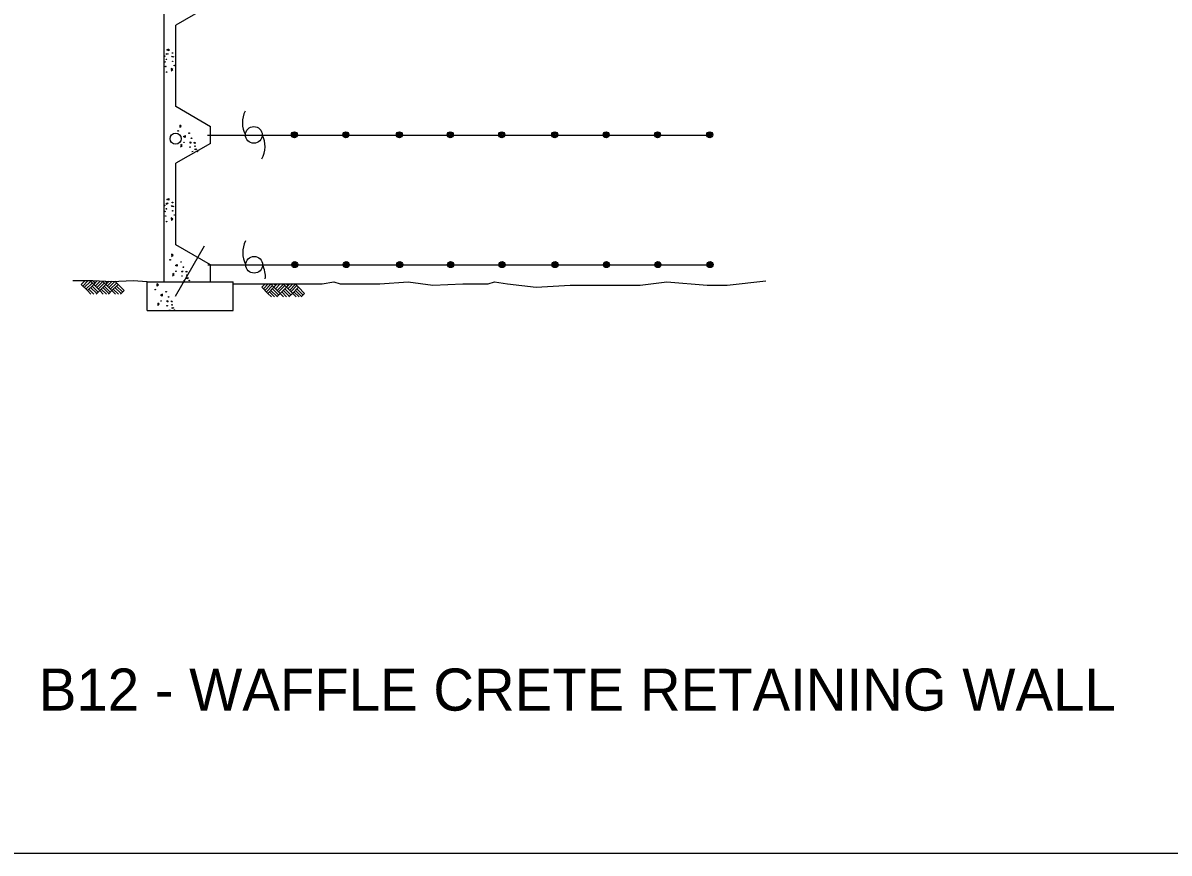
# Model space of a CAD drawing. Extents: x -0.04 to 2.79, y -0.02 to 1.81.
# Drawn here: x 0.1828 to 0.4662, y 0.4885 to 0.6938 of the extents above; entities that cross this region are included whole.
import ezdxf

# ---------------------------------------------------------------- set-up
doc = ezdxf.new("R2010")
doc.units = 0
doc.layers.add('Level 1', color=7, linetype='Continuous')
doc.layers.add('Level 2', color=7, linetype='Continuous')

msp = doc.modelspace()

# ---------------------------------------------------------------- linework, layer by layer
msp.add_line((0.11656352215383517, 0.48847341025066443), (2.517841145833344, 0.48847341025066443))
at = {"layer": 'Level 1'}
for p, q in [((0.21775933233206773, 0.6298094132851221), (0.21775933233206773, 0.8241991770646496)), ((0.22917392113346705, 0.6982285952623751), (0.2206300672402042, 0.6933073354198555)), ((0.2206300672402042, 0.6731438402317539), (0.2206300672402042, 0.6933073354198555)), ((0.22917392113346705, 0.668154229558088), (0.2206300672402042, 0.6731438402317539)), ((0.228490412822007, 0.6661037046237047), (0.3526155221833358, 0.6661037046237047)), ((0.22917392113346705, 0.6639848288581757), (0.22917392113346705, 0.6682909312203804)), ((0.22917392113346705, 0.6640531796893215), (0.2206300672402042, 0.6591319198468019)), ((0.2206300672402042, 0.6389684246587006), (0.2206300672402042, 0.6591319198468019)), ((0.2276702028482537, 0.6386266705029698), (0.2204933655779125, 0.6261868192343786)), ((0.22917392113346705, 0.6339788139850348), (0.2206300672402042, 0.6389684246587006)), ((0.22855876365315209, 0.6339788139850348), (0.35268387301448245, 0.6339788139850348)), ((0.22917392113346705, 0.6298094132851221), (0.22917392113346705, 0.6341155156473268)), ((0.1972540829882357, 0.6291259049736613), (0.19807429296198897, 0.6299461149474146)), ((0.19882615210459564, 0.6276221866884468), (0.1972540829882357, 0.6291259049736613)), ((0.19766418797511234, 0.6287157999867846), (0.19882615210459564, 0.6299461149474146)), ((0.19800594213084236, 0.6283740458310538), (0.19957801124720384, 0.6298777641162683)), ((0.198416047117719, 0.6279639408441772), (0.19991976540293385, 0.6294676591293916)), ((0.19882615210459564, 0.6276221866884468), (0.2003298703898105, 0.6291259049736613)), ((0.2003298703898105, 0.6291259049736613), (0.19950966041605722, 0.6299461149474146)), ((0.20067162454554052, 0.6294676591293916), (0.2002615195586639, 0.6299461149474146)), ((0.2003298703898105, 0.6291259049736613), (0.20108172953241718, 0.6299461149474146)), ((0.2003298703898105, 0.6291259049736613), (0.20108172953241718, 0.6299461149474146)), ((0.20183358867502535, 0.6276221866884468), (0.2003298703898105, 0.6291259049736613)), ((0.20067162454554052, 0.6287157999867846), (0.20190193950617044, 0.6299461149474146)), ((0.20108172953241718, 0.6298777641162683), (0.2010133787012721, 0.6299461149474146)), ((0.20108172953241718, 0.6283740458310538), (0.20258544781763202, 0.6298777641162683)), ((0.20142348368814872, 0.6279639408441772), (0.20292720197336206, 0.6294676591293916)), ((0.20183358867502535, 0.6276221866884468), (0.2033373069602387, 0.6291259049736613)), ((0.2033373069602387, 0.6291259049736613), (0.2025170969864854, 0.6299461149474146)), ((0.20367906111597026, 0.6294676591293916), (0.2032689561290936, 0.6299461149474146)), ((0.2033373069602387, 0.6291259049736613), (0.20415751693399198, 0.6299461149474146)), ((0.2033373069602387, 0.6291259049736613), (0.20415751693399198, 0.6299461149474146)), ((0.20572958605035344, 0.6267336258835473), (0.2033373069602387, 0.6291259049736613)), ((0.20367906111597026, 0.6287157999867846), (0.20490937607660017, 0.6299461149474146)), ((0.2040891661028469, 0.6298777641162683), (0.20402081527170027, 0.6299461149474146)), ((0.2040891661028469, 0.6283740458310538), (0.20559288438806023, 0.6298777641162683)), ((0.2044309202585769, 0.6279639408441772), (0.20593463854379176, 0.6294676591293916)), ((0.20484102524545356, 0.6276221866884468), (0.2063447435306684, 0.6291259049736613)), ((0.2063447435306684, 0.6291259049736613), (0.20552453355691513, 0.6299461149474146)), ((0.20784846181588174, 0.6276221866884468), (0.2063447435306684, 0.6291259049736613)), ((0.2135215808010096, 0.6298094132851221), (0.23484704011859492, 0.6298094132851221)), ((0.2135215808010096, 0.6227009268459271), (0.2135215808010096, 0.6298094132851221)), ((0.23484704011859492, 0.6227009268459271), (0.23484704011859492, 0.6298094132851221)), ((0.2418871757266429, 0.6284423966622), (0.24270738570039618, 0.6292626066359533)), ((0.24229728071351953, 0.6281006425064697), (0.24345924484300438, 0.6292626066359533)), ((0.2426390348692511, 0.627690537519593), (0.2441427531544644, 0.6291942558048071)), ((0.2448946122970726, 0.6284423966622), (0.2441427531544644, 0.6292626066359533)), ((0.2448946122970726, 0.6284423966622), (0.2457148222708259, 0.6292626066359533)), ((0.24530471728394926, 0.6288525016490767), (0.2448946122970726, 0.6292626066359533)), ((0.2448946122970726, 0.6284423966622), (0.2457148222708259, 0.6292626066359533)), ((0.24530471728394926, 0.6281006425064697), (0.24646668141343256, 0.6292626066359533)), ((0.2457148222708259, 0.6291942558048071), (0.24564647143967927, 0.6292626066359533)), ((0.2457148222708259, 0.627690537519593), (0.24721854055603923, 0.6291942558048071)), ((0.2479703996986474, 0.6284423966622), (0.24715018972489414, 0.6292626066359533)), ((0.24831215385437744, 0.6288525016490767), (0.2479020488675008, 0.6292626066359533)), ((0.2479703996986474, 0.6284423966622), (0.2487906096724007, 0.6292626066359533)), ((0.2479703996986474, 0.6284423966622), (0.2487906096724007, 0.6292626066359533)), ((0.24831215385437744, 0.6281006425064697), (0.24954246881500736, 0.6292626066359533)), ((0.24872225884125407, 0.6291942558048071), (0.24865390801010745, 0.6292626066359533)), ((0.24872225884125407, 0.627690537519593), (0.25022597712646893, 0.6291942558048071)), ((0.2509778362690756, 0.6284423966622), (0.25015762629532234, 0.6292626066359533)), ((0.19964636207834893, 0.6267336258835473), (0.19882615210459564, 0.6276221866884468)), ((0.20039822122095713, 0.6267336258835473), (0.1991679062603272, 0.6279639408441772)), ((0.20108172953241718, 0.6268703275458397), (0.19957801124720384, 0.6283740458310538)), ((0.20142348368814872, 0.6272120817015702), (0.19991976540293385, 0.6287157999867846)), ((0.20094502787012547, 0.6267336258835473), (0.20183358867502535, 0.6276221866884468)), ((0.20265379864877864, 0.6267336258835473), (0.20183358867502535, 0.6276221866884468)), ((0.20347400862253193, 0.6267336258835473), (0.2021753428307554, 0.6279639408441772)), ((0.2040891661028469, 0.6268703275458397), (0.20258544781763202, 0.6283740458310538)), ((0.2044309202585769, 0.6272120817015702), (0.20292720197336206, 0.6287157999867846)), ((0.20395246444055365, 0.6267336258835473), (0.20484102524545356, 0.6276221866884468)), ((0.2064814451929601, 0.6267336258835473), (0.20518277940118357, 0.6279639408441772)), ((0.20709660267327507, 0.6268703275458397), (0.20559288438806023, 0.6283740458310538)), ((0.20750670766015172, 0.6272120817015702), (0.20593463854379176, 0.6287157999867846)), ((0.20695990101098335, 0.6267336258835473), (0.20784846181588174, 0.6276221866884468)), ((0.24339089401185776, 0.6269386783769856), (0.2418871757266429, 0.6284423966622)), ((0.24304913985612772, 0.6273487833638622), (0.24455285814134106, 0.6288525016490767)), ((0.24339089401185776, 0.6269386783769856), (0.2448946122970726, 0.6284423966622)), ((0.24427945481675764, 0.6260501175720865), (0.24339089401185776, 0.6269386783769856)), ((0.2450313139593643, 0.6260501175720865), (0.2438009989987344, 0.6273487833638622)), ((0.2457148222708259, 0.6261868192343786), (0.2441427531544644, 0.627690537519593)), ((0.2460565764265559, 0.6265969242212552), (0.24455285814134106, 0.6281006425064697)), ((0.24646668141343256, 0.6269386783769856), (0.2448946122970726, 0.6284423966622)), ((0.24557812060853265, 0.6260501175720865), (0.24646668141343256, 0.6269386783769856)), ((0.2460565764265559, 0.6273487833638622), (0.24756029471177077, 0.6288525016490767)), ((0.24646668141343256, 0.6269386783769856), (0.2479703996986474, 0.6284423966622)), ((0.24728689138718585, 0.6260501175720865), (0.24646668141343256, 0.6269386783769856)), ((0.2480387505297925, 0.6260501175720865), (0.24680843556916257, 0.6273487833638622)), ((0.24872225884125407, 0.6261868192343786), (0.24721854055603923, 0.627690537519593)), ((0.2490640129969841, 0.6265969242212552), (0.24756029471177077, 0.6281006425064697)), ((0.2503626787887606, 0.6260501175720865), (0.2479703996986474, 0.6284423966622)), ((0.24858555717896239, 0.6260501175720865), (0.24947411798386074, 0.6269386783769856)), ((0.2490640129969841, 0.6273487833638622), (0.25056773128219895, 0.6288525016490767)), ((0.24947411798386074, 0.6269386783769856), (0.2509778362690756, 0.6284423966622)), ((0.2511145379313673, 0.6260501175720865), (0.2498158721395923, 0.6273487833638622)), ((0.2517296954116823, 0.6261868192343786), (0.25022597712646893, 0.627690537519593)), ((0.25207144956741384, 0.6265969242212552), (0.25056773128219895, 0.6281006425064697)), ((0.25248155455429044, 0.6269386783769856), (0.2509778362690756, 0.6284423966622)), ((0.25159299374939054, 0.6260501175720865), (0.25248155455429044, 0.6269386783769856)), ((0.2135215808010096, 0.6227009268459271), (0.23484704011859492, 0.6227009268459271))]:
    msp.add_line(p, q, dxfattribs=at)
for points in [[(0.2135215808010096, 0.6298094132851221), (0.21010403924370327, 0.6300828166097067), (0.20484102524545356, 0.6298094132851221), (0.20012481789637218, 0.6300828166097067), (0.1951352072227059, 0.6300828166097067)], [(0.23484704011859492, 0.6292626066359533), (0.2376494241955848, 0.6292626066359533), (0.24243398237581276, 0.6292626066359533), (0.24632997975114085, 0.6292626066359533), (0.2528916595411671, 0.6292626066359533), (0.2568560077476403, 0.6292626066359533), (0.2597267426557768, 0.6298094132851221), (0.2612988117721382, 0.6292626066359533), (0.26792884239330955, 0.6292626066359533), (0.27107298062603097, 0.6292626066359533), (0.27811311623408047, 0.6298094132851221), (0.2841963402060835, 0.6289892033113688), (0.291578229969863, 0.6292626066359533), (0.2978665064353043, 0.6292626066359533), (0.2994385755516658, 0.6298094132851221), (0.3026510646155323, 0.6292626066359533), (0.3096912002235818, 0.6285107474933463), (0.3180983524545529, 0.6289892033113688), (0.32677890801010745, 0.6289892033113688), (0.33545946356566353, 0.6289892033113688), (0.3420211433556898, 0.6298094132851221), (0.3520003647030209, 0.6289892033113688), (0.35698997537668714, 0.6289892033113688), (0.3664907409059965, 0.6300828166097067)]]:
    msp.add_lwpolyline(points, dxfattribs=at)
for centre, radius in [((0.2205845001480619, 0.665208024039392), 0.0013812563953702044), ((0.23991746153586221, 0.6661378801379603), 0.002070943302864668), ((0.2499598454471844, 0.6661744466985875), 0.0007409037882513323), ((0.2499598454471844, 0.6661744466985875), 0.0005745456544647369), ((0.2499598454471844, 0.6661744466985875), 0.0004212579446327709), ((0.2499598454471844, 0.6661744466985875), 0.0002128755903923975), ((0.26267167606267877, 0.6661744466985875), 0.0007409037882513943), ((0.26267167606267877, 0.6661744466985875), 0.0005745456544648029), ((0.26267167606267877, 0.6661744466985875), 0.0004212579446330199), ((0.26267167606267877, 0.6661744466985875), 0.0002128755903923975), ((0.2759146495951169, 0.6661744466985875), 0.0007409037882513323), ((0.2759146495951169, 0.6661744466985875), 0.0005745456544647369), ((0.2759146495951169, 0.6661744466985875), 0.0004212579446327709), ((0.2759146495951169, 0.6661744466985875), 0.0002128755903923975), ((0.2884940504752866, 0.6661744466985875), 0.0007409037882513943), ((0.2884940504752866, 0.6661744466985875), 0.0005745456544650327), ((0.2884940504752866, 0.6661744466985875), 0.00042125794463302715), ((0.2884940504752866, 0.6661744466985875), 0.0002128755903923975), ((0.30120730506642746, 0.6661744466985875), 0.0007409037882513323), ((0.30120730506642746, 0.6661744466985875), 0.0005745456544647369), ((0.30120730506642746, 0.6661744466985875), 0.0004212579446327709), ((0.30120730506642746, 0.6661744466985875), 0.0002128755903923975), ((0.31431784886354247, 0.6661744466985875), 0.0007409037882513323), ((0.31431784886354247, 0.6661744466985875), 0.0005745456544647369), ((0.31431784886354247, 0.6661744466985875), 0.0004212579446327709), ((0.31431784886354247, 0.6661744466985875), 0.00021287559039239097), ((0.32702967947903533, 0.6661744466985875), 0.0007409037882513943), ((0.32702967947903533, 0.6661744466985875), 0.0005745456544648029), ((0.32702967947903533, 0.6661744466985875), 0.0004212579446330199), ((0.32702967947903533, 0.6661744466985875), 0.00021287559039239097), ((0.3397429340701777, 0.6661744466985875), 0.0007409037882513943), ((0.3397429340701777, 0.6661744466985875), 0.0005745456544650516), ((0.3397429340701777, 0.6661744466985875), 0.00042125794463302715), ((0.3397429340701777, 0.6661744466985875), 0.00021287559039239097), ((0.3526455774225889, 0.6661744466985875), 0.0007409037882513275), ((0.3526455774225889, 0.6661744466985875), 0.0005745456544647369), ((0.3526455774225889, 0.6661744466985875), 0.00042125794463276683), ((0.3526455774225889, 0.6661744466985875), 0.0002128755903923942), ((0.24000930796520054, 0.6340201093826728), 0.0020709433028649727), ((0.25004386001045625, 0.6340566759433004), 0.0007409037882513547), ((0.26275569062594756, 0.6340566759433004), 0.0007409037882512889), ((0.27599866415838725, 0.6340566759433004), 0.0007409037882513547), ((0.28857806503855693, 0.6340566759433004), 0.0007409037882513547), ((0.3012913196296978, 0.6340566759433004), 0.0007409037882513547), ((0.3144018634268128, 0.6340566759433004), 0.0007409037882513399), ((0.32711369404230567, 0.6340566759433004), 0.0007409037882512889), ((0.33982694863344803, 0.6340566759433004), 0.0007409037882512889), ((0.35272959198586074, 0.6340566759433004), 0.000740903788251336), ((0.25004386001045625, 0.6340566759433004), 0.0005745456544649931), ((0.25004386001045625, 0.6340566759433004), 0.00042125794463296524), ((0.25004386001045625, 0.6340566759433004), 0.0002128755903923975), ((0.26275569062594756, 0.6340566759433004), 0.0005745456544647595), ((0.26275569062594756, 0.6340566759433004), 0.00042125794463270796), ((0.26275569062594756, 0.6340566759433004), 0.0002128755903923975), ((0.27599866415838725, 0.6340566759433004), 0.0005745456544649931), ((0.27599866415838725, 0.6340566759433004), 0.00042125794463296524), ((0.27599866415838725, 0.6340566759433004), 0.0002128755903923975), ((0.28857806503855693, 0.6340566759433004), 0.0005745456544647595), ((0.28857806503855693, 0.6340566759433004), 0.00042125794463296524), ((0.28857806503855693, 0.6340566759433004), 0.0002128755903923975), ((0.3012913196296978, 0.6340566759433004), 0.0005745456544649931), ((0.3012913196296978, 0.6340566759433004), 0.00042125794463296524), ((0.3012913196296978, 0.6340566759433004), 0.0002128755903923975), ((0.3144018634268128, 0.6340566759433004), 0.0005745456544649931), ((0.3144018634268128, 0.6340566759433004), 0.00042125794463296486), ((0.3144018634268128, 0.6340566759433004), 0.00021287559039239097), ((0.32711369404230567, 0.6340566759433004), 0.0005745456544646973), ((0.32711369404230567, 0.6340566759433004), 0.0004212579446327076), ((0.32711369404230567, 0.6340566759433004), 0.00021287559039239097), ((0.33982694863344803, 0.6340566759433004), 0.0005745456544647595), ((0.33982694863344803, 0.6340566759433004), 0.0004212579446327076), ((0.33982694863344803, 0.6340566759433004), 0.00021287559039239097), ((0.35272959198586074, 0.6340566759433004), 0.0005745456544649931), ((0.35272959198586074, 0.6340566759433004), 0.0004212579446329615), ((0.35272959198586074, 0.6340566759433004), 0.0002128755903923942)]:
    msp.add_circle(centre, radius, dxfattribs=at)
for centre, radius, start, end in [((0.24346539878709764, 0.6691370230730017), 0.006373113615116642, 152.8748638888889, 208.15988888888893), ((0.23631612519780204, 0.663223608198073), 0.006373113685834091, 331.8401111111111, 27.125136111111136), ((0.24355724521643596, 0.6370192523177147), 0.006373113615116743, 152.8748638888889, 208.15988888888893), ((0.23640797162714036, 0.6311058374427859), 0.006373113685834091, 354.5283111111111, 27.125136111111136)]:
    msp.add_arc(centre, radius, start, end, dxfattribs=at)
at = {"layer": 'Level 2'}
for points in [[(0.2187162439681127, 0.6861988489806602), (0.21830613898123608, 0.6859937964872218), (0.21830613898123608, 0.6862671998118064), (0.2187162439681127, 0.6861988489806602)], [(0.21892129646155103, 0.6873608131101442), (0.21892129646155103, 0.6869507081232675), (0.2184428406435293, 0.6872241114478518), (0.21892129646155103, 0.6874291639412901)], [(0.22001490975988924, 0.6854469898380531), (0.2197415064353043, 0.6854469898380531), (0.2196048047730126, 0.6856520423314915), (0.22015161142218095, 0.6854469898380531)], [(0.2194681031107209, 0.6820294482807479), (0.21987820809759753, 0.6823028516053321), (0.2194681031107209, 0.6825762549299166), (0.219536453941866, 0.6819610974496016)], [(0.2215869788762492, 0.6680175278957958), (0.22199708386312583, 0.6682909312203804), (0.2215869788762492, 0.6685643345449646), (0.22165532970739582, 0.6679491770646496)], [(0.22295399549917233, 0.6659670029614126), (0.22295399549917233, 0.6654885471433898), (0.2225438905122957, 0.6657619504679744), (0.22302234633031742, 0.666035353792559)], [(0.2217920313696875, 0.6632329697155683), (0.22220213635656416, 0.6635063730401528), (0.22186038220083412, 0.6637797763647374), (0.22192873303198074, 0.6631646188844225)], [(0.22438936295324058, 0.6641215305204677), (0.22418431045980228, 0.6641215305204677), (0.22418431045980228, 0.6643949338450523), (0.22438936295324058, 0.6641215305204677)], [(0.2254829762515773, 0.6641215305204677), (0.22527792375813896, 0.6640531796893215), (0.22520957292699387, 0.6643265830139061), (0.2254829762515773, 0.664189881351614)], [(0.22493616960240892, 0.6620026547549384), (0.2245944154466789, 0.6619343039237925)], [(0.22582473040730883, 0.6626178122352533), (0.2254146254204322, 0.662412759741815), (0.2254146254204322, 0.6626861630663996), (0.22582473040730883, 0.6626178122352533)], [(0.2187162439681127, 0.6492210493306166), (0.21830613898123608, 0.648947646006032), (0.21830613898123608, 0.6492894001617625), (0.2187162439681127, 0.6492210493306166)], [(0.21892129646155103, 0.6503830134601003), (0.21892129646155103, 0.6499729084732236), (0.2184428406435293, 0.650177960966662), (0.21892129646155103, 0.6504513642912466)], [(0.22001490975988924, 0.6484691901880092), (0.2197415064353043, 0.6484691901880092), (0.2196048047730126, 0.6486742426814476), (0.22015161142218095, 0.6484691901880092)], [(0.2194681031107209, 0.645051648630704), (0.21987820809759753, 0.6453250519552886), (0.2194681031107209, 0.6455984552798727), (0.219536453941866, 0.6449832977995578)], [(0.219536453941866, 0.6360976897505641), (0.22001490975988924, 0.6363710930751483), (0.2196048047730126, 0.6366444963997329), (0.21967315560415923, 0.6360293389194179)], [(0.22097182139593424, 0.634047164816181), (0.22097182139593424, 0.6336370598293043), (0.22056171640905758, 0.6338421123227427), (0.22097182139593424, 0.6341155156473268)], [(0.22240718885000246, 0.632201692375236), (0.22213378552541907, 0.6322700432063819), (0.22220213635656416, 0.6325434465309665), (0.22240718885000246, 0.6322700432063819)], [(0.2235008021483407, 0.6322700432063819), (0.22322739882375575, 0.632201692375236), (0.22315904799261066, 0.6324067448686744), (0.2235008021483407, 0.6323383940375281)], [(0.21591385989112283, 0.6287841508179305), (0.2163239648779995, 0.6290575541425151), (0.21591385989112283, 0.6293309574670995), (0.21598221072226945, 0.6287157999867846)], [(0.21980985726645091, 0.6313131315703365), (0.22021996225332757, 0.6315865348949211), (0.21987820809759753, 0.6318599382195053), (0.21987820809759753, 0.6312447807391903)], [(0.22288564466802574, 0.6300828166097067), (0.2225438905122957, 0.6300144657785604)], [(0.22377420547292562, 0.6307663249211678), (0.22343245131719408, 0.6305612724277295), (0.22343245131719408, 0.6308346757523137), (0.22377420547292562, 0.6307663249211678)], [(0.21728087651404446, 0.6267336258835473), (0.21728087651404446, 0.6262551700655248), (0.21687077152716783, 0.6265285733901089), (0.21734922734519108, 0.6268019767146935)], [(0.21611891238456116, 0.6239995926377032), (0.21652901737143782, 0.6242729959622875), (0.21618726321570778, 0.624546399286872), (0.21625561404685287, 0.623931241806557)], [(0.2187162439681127, 0.6248881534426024), (0.21851119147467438, 0.6248881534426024), (0.21851119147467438, 0.625161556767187), (0.2187162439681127, 0.6248881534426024)], [(0.21980985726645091, 0.6248881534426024), (0.2196048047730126, 0.6248198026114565), (0.219536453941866, 0.6250932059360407), (0.21980985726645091, 0.6249565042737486)], [(0.22015161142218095, 0.6233844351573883), (0.2197415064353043, 0.62317938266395), (0.2197415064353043, 0.6234527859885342), (0.22015161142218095, 0.6233844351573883)], [(0.21926305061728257, 0.6227692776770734), (0.21892129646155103, 0.6227009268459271)]]:
    msp.add_lwpolyline(points, dxfattribs=at)
for centre, radius in [((0.21980549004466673, 0.6864112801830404), 7.404673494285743e-05), ((0.21785490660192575, 0.6856301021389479), 7.404673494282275e-05), ((0.21795312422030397, 0.6842053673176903), 7.404673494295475e-05), ((0.2181402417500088, 0.6830713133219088), 7.404673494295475e-05), ((0.21831766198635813, 0.684836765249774), 7.404673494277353e-05), ((0.21984999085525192, 0.6843466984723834), 7.404673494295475e-05), ((0.22026219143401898, 0.6833063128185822), 7.404673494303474e-05), ((0.21834738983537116, 0.681675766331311), 7.404673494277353e-05), ((0.2212211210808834, 0.6671185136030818), 7.404673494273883e-05), ((0.2239246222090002, 0.666583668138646), 7.404673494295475e-05), ((0.22265972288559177, 0.6643016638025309), 7.404673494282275e-05), ((0.22415653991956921, 0.6631349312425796), 7.404673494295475e-05), ((0.22451663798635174, 0.665307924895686), 7.404673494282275e-05), ((0.22538396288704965, 0.6633470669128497), 7.404673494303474e-05), ((0.22595889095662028, 0.662041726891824), 7.404673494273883e-05), ((0.21980549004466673, 0.6494292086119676), 7.404673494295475e-05), ((0.21785490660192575, 0.6486480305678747), 7.404673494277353e-05), ((0.21795312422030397, 0.6472232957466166), 7.404673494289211e-05), ((0.2181402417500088, 0.6460892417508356), 7.404673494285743e-05), ((0.21831766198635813, 0.6478546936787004), 7.404673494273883e-05), ((0.21984999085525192, 0.6473646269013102), 7.404673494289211e-05), ((0.22026219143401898, 0.646324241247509), 7.404673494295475e-05), ((0.21834738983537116, 0.6446936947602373), 7.404673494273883e-05), ((0.21922755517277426, 0.635228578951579), 7.404673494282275e-05), ((0.22066615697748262, 0.6324117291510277), 7.404673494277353e-05), ((0.22193105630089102, 0.6346937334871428), 7.404673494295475e-05), ((0.2225230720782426, 0.6334179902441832), 7.404673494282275e-05), ((0.22216297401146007, 0.6312449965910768), 7.404673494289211e-05), ((0.22339039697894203, 0.6314571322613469), 7.404673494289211e-05), ((0.2239653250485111, 0.6301517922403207), 7.404673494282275e-05), ((0.21554942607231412, 0.6278694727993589), 7.404673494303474e-05), ((0.21825292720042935, 0.627334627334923), 7.404673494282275e-05), ((0.21698802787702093, 0.6250526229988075), 7.404673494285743e-05), ((0.2184848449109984, 0.6238858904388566), 7.404673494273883e-05), ((0.21884494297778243, 0.6260588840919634), 7.404673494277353e-05), ((0.21971226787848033, 0.6240980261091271), 7.404673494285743e-05), ((0.22028719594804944, 0.6227926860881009), 7.404673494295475e-05)]:
    msp.add_circle(centre, radius, dxfattribs=at)

# ---------------------------------------------------------------- texts
msp.add_text('B12 - WAFFLE CRETE RETAINING WALL', height=0.010416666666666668).set_placement((0.18676820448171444, 0.5237134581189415))

doc.saveas('drawing.dxf')
